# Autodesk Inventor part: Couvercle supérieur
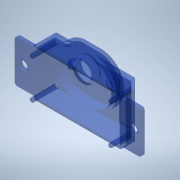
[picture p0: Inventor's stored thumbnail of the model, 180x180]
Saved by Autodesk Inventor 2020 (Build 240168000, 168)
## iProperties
Created: 2002-01
Part Number: Couvercle supérieur
Material: Générique
Document SubType Name: Modélisation
Designer: Philippe
Density: 1 g/cm^3
Appearance: Bleu (transparent)
Shininess: 20.0
Angle Display Precision: 2
Document Length Units: 11269
Document Angle Units: 11279
Document Time Units: 11290
Document Mass Units: 11283
Document Length Units Precision: 3
Document Angle Units Precision: 2
Density: 0.0
Volumn: 0.0
Area: 0.0
PropertySet Name: Model Information
Control State: 0
Master: False
Checked Out: False
Author: Philippe
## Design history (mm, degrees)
sketch "Esquisse1"
  geometry: L1 (-1.506, 0)-(28.494, 0); L2 (28.494, 0)-(28.494, 0.8); L3 (28.494, 0.8)-(23.994, 0.8); L4 (23.994, 0.8)-(23.994, 5); L5 (23.994, 5)-(2.994, 5); L6 (2.994, 5)-(2.994, 0.8); L7 (2.994, 0.8)-(-1.506, 0.8); L8 (-1.506, 0.8)-(-1.506, 0); L9 (2.994, 0.8)-(2.994, 0); L10 (23.994, 0.8)-(23.994, 0)
  constraints: 20 end point, 8 parallel, 2 point on line, 1 collinear, 1 horizontal, 1 perpendicular, 1 other
  dimensions: "d0" = 4.5 distance of L2.end L3.end; "d1" = 4.5 distance of L6.end L7.end (= d0); "d2" = 30 distance of L1.start L1.end; "d3" = 0.8 distance between parallel lines of L3 L1; "d4" = 5 distance between parallel lines of L5 L1
extrude "Extrusion1" new body sketch "Esquisse1" stored distance "d5" = 11.4; taper "d6" = 0 deg
extrude "Extrusion2" join sketch "Esquisse1" stored distance "d7" = 10; taper "d8" = 0 deg
fillet "Congé1" dims "d9" = 0.6
fillet "Congé2" dims "d10" = 0.6
chamfer "Chanfrein1" distance "d11" = 2; stored, may be unused: second distance "d12" = 2, angle "d81" = 45 deg
sketch "Esquisse2"
  geometry: L1 (19, 10.8)-(0.6, 10.8) reference; L2 (0, 10.2)-(0, 0) reference; L3 (0.6, -0.6)-(19, -0.6) reference; A1 r 5.8 centre (5.8, 5.1) between (4.728, 10.8) and (4.728, -0.6); A2 r 5.7 centre (8.9, 5.1) between (8.9, -0.6) and (8.9, 10.8)
  constraints: 4 point on circle, 4 point on line, 3 tangent, 2 centre point, 1 horizontal alignment
  dimensions: "d13" = 5.8 radius of A1; "d14" = 14.6 dimension on A2 A1
extrude "Extrusion3" join sketch "Esquisse2" distance "d15" = 2.2; taper "d16" = 0 deg
fillet "Congé3" dims "d17" = 0.5
feature "Coque1" dims "d18" = 0.6, "d19" = 0.8
sketch "Esquisse3"
  geometry: C1 r 2.6 at (5.8, 5.1); A1 r 5.3 centre (5.8, 5.1) between (4.775, 10.3) and (4.775, -0.1) reference
  constraints: 1 centre point, 1 coincident
  dimensions: "d20" = 5.2 diameter of C1
extrude "Extrusion4" join sketch "Esquisse3" distance "d21" = 0.3; taper "d22" = 0 deg
sketch "Esquisse5"
  geometry: C1 r 2.6 at (1.015, -5.1); C2 r 2.6 at (1.015, -5.1) reference; A1 r 5.2 centre (1.015, -5.1) between (0, 0) and (0, -10.2) reference
  constraints: 1 centre point, 1 coincident, 1 concentric
extrude "Extrusion5" join sketch "Esquisse5" distance "d23" = 0.7; taper "d24" = 0 deg
sketch "Esquisse6"
  geometry: C1 r 2.6 at (0, 0) reference; 1 further point
  constraints: 1 coincident
hole "Perçage1" sketch "Esquisse6" at (0, 0), (0, 0) diameter "d25" = 4; stored, may be unused: countersink angle "d29" = 82 deg, drill point angle "d31" = 118 deg; dims "d26" = 6, "d27" = 4, "d28" = 2, "d30" = 8
sketch "Esquisse8"
  geometry: L1 (0, 11.4)-(0, 0) reference; L2 (-18.4, 0.6)-(1.4, 0.6) reference; L3 (1.4, 10.8)-(-18.4, 10.8) reference; L4 (-1, 0.6)-(-3.5, 0.6); L5 (-3.5, 0.6)-(-3.5, 10.8); L6 (-3.5, 10.8)-(-1, 10.8); L7 (-1, 10.8)-(-1, 0.6)
  constraints: 8 end point, 2 parallel, 2 point on line, 1 horizontal, 1 perpendicular
  dimensions: "d41" = 2.5 distance between parallel lines of L5 L7; "d42" = 1 distance between parallel lines of L1 L7
extrude "Extrusion6" cut sketch "Esquisse8" distance "d43" = 0.2; taper "d44" = 0 deg
sketch "Esquisse9"
  geometry: C1 r 2.6 at (1.015, -5.1) reference; C2 r 1 at (7.015, -5.1); C3 r 0.5 at (7.015, -5.1)
  constraints: 2 centre point, 1 coincident, 1 horizontal alignment
  dimensions: "d45" = 6 distance of C1.centre C2.centre; "d46" = 2 diameter of C2; "d47" = 1 diameter of C3
extrude "Extrusion7" join sketch "Esquisse9" distance "d48" = 0.3; taper "d49" = 0 deg
sketch "Esquisse10"
  geometry: L1 (4.115, -10.2)-(0, -10.2) reference; L2 (-2.076, -4.272)-(-0.917, -4.582); L3 (-2.076, -5.928)-(-1.497, -5.773); L4 (1.015, -5.1)-(-3.261, -5.1); L5 (-0.917, -4.582)-(-1.497, -4.427); L6 (-1.497, -5.773)-(-0.917, -5.618); A1 r 5.2 centre (1.015, -5.1) between (0, 0) and (0, -10.2) reference; A2 r 3.2 centre (1.015, -5.1) between (-2.076, -4.272) and (-2.076, -5.928); A3 r 2 centre (1.015, -5.1) between (-0.917, -4.582) and (-0.917, -5.618) reference; A4 r 2.6 centre (1.015, -5.1) between (-1.497, -5.773) and (-1.497, -4.427) reference; 1 further point
  constraints: 10 end point, 6 point on circle, 2 point on line, 1 centre point, 1 collinear, 1 concentric, 1 midpoint, 1 parallel, 3 other
  dimensions: "d50" = 3.2 radius of A2; "d51" = 30 deg angle of L3 L2
extrude "Extrusion8" join sketch "Esquisse10" distance "d52" = 1.2; taper "d53" = 0 deg
node "Plan de construction1"
sketch "Esquisse12"
  geometry: L1 (-0.6, -10.6)-(-0.6, -0.6) reference; L2 (20.4, -0.6)-(20.4, -10.6) reference; L3 (0, -11.4)-(19.8, -11.4) reference; L4 (19.8, 0)-(0, 0) reference; C1 r 0.5 at (0.6, -1.2); C2 r 0.5 at (0.6, -10.2); C3 r 0.5 at (19.2, -10.2); C4 r 0.5 at (19.2, -1.2)
  constraints: 4 centre point, 3 equal radius
  dimensions: "d58" = 1 diameter of C1; "d62" = 1.2 distance from line of L1 C2.centre; "d63" = 1.2 distance from line of L1 C1.centre; "d64" = 1.2 distance from line of L2 C3.centre; "d65" = 1.2 distance from line of L2 C4.centre; "d66" = 1.2 distance from line of C2.centre L3; "d67" = 1.2 distance from line of L3 C3.centre; "d68" = 1.2 distance from line of C4.centre L4; "d70" = 1.2 distance from line of C1.centre L4
extrude "Extrusion10" join sketch "Esquisse12" stored distance "d59" = 6.2; taper "d60" = 0 deg
fillet "Congé4" dims "d61" = 0.3
sketch "Esquisse13"
  geometry: L1 (24.9, -1.3)-(24.9, -10.1) reference; L2 (-5.1, -1.3)-(-5.1, -10.1) reference; A1 r 2 centre (5.2, -5.7) between (3.268, -6.218) and (3.268, -5.182) reference; 2 further points
  constraints: 2 horizontal alignment
  dimensions: "d72" = 2 distance from line of point (-3.1, -5.7) L2; "d73" = 2 distance from line of point (22.9, -5.7) L1
hole "Perçage3" sketch "Esquisse13" at (-3.1, -5.7), (22.9, -5.7) diameter "d74" = 2; stored, may be unused: countersink angle "d78" = 82 deg, drill point angle "d80" = 118 deg; dims "d75" = 6, "d76" = 4, "d77" = 2, "d79" = 8
node "Solide1"
node "Corps solides"
node "Corps surfaciques"
other parameters: "d57" = 1.8
